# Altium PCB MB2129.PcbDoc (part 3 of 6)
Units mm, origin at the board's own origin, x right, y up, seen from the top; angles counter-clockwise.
Board outline 70 x 133.34 mm, 6 copper layers (Top Layer, Signal Layer 1, Signal Layer 2, Signal Layer 3, Signal Layer 4, Bottom Layer), stack 1.57 mm thick; 377 components, 289 nets, 1482 pads, 1373 vias.
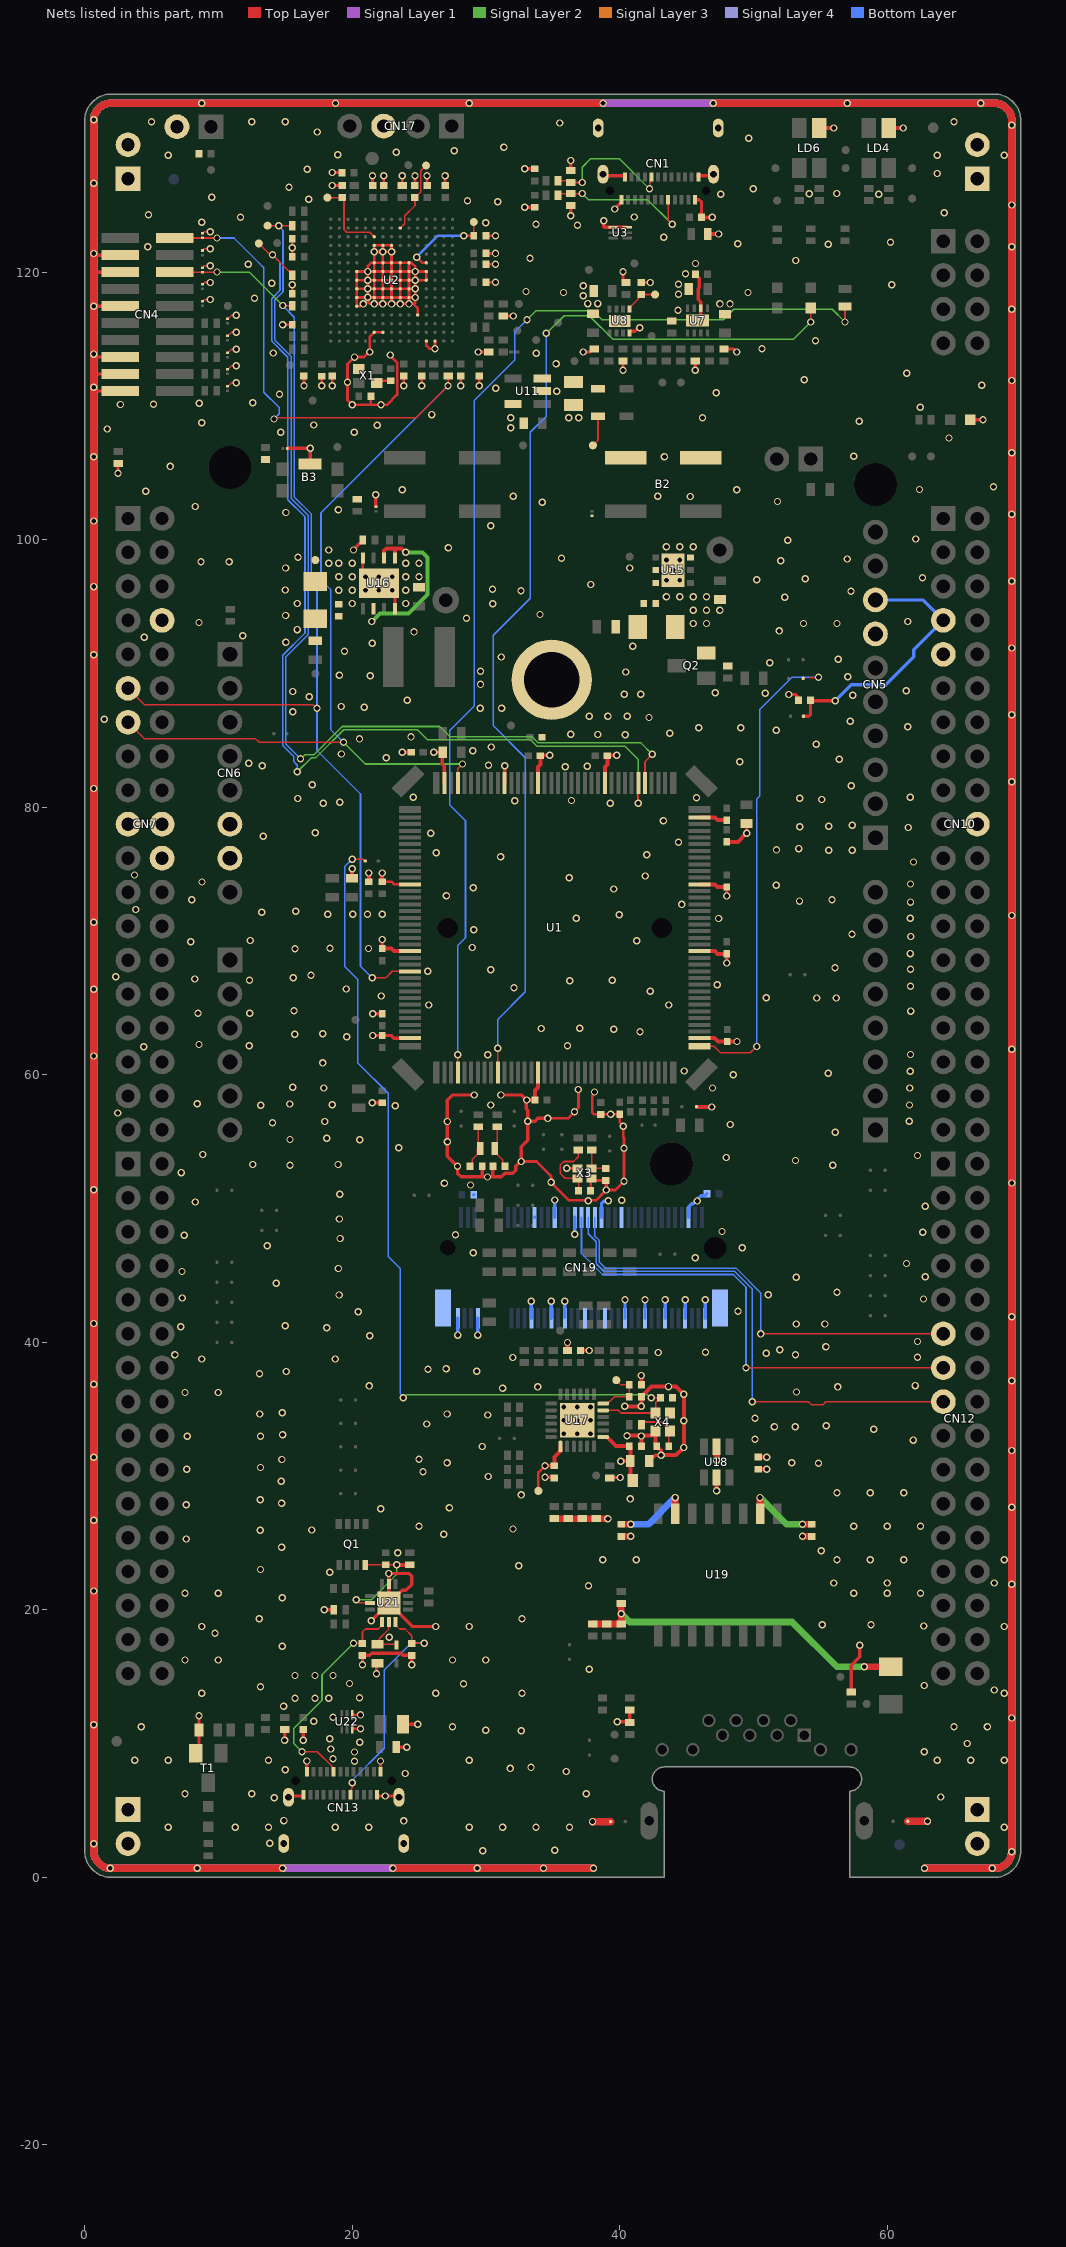
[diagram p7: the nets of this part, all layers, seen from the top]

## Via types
v1: diameter 0.55, hole 0.35, Top Layer to Bottom Layer, tented both sides, 1373 vias

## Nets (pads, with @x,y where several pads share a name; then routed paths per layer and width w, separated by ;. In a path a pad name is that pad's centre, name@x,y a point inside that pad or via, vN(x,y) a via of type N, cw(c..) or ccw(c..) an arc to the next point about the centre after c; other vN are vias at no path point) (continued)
DBGIN.SWDIO: CN4.2 CN7.13 R45.2 U1.105 U24.1 | length 93.5
  Top Layer w0.12: CN7.13@3.246,86.37 4.466,85.15 12.774,85.15 13.049,84.875 17.35,84.875 v1(19.35,84.875) ; CN4.2@6.735,122.565 6.752,122.581 U24.1@8.8,122.581 v1(9.9,122.581) ; v1(14.155,109.046) 14.235,109.127 24.767,109.127 v1(27.17,111.53) ; v1@27.175,111.53 R45.2@27.175,112.25 ; U1.105@27.9,81.825 27.9,82.9 v1(28.25,83.25)
  Signal Layer 2 w0.12: v1(19.35,84.875) 20.975,83.25 v1(28.25,83.25)
  Bottom Layer w0.12: v1(9.9,122.581) 11.168,122.581 13.075,120.675 13.395,120.355 13.395,111.055 14.55,109.9 14.55,109.441 v1(14.155,109.046) ; v1(19.35,84.875) 18.39,85.835 18.39,96.295 17.675,97.01 17.675,102.035 v1(27.17,111.53)
DBGIN.SWO: CN4.6 CN7.11 R22.2 U1.133 U10.1 | length 80.6
  Top Layer w0.12: CN7.11@3.246,88.91 4.489,87.667 17.09,87.667 17.331,87.425 v1(17.375,87.425) ; CN4.6@6.735,120.025 6.742,120.031 U10.1@8.8,120.031 v1(9.9,120.031) ; v1@14.8,117.525 R22.2@15.525,117.525 ; v1(21.5,67.275) 22.526,67.275 23.001,67.75 U1.133@24.325,67.75
  Signal Layer 2 w0.12: v1(9.9,120.031) 12.304,120.031 v1(14.805,117.53)
  Bottom Layer w0.12: v1(14.805,117.53) 15.675,116.66 15.675,103.214 16.955,101.934 16.955,96.712 17.375,96.292 v1(17.375,87.425) 17.375,84.264 20.625,81.014 20.625,68.125 v1@21.45,67.3 ; v1@21.45,67.275 v1(21.5,67.275)
DBGIN.VCP_RX: R20.2 TP17.1 U1.78 | length 77.3
  Top Layer w0.12: TP17.1@13.025,122.175 13.793,121.407 13.968,121.407 15.285,120.09 15.33,120.09 15.525,119.895 R20.2@15.525,119.8 ; v1(41.4,80.325) U1.78@41.4,81.825
  Signal Layer 2 w0.12: v1(15.905,82.671) 16.939,83.705 17.253,83.705 19.363,85.815 24.887,85.815 25.652,85.05 33.35,85.05 33.825,84.575 40.409,84.575 41.4,83.584 v1(41.4,80.325)
  Bottom Layer w0.12: v1(14.05,121.325) 14.61,120.765 14.61,118.674 13.98,118.044 13.98,114.884 15.195,113.669 15.195,103.016 16.475,101.736 16.475,93.039 14.81,91.374 14.81,84.636 15.638,83.808 15.638,83.432 15.905,83.164 v1(15.905,82.671)
DBGIN.VCP_TX: R16.2 TP15.1 U1.77 | length 74.6
  Top Layer w0.12: TP15.1@13.925,123.5 v1(14.525,123.5) R16.2@15.521,123.5 ; U1.77@41.9,81.825 41.9,83.425 v1(42.45,83.975)
  Signal Layer 2 w0.12: v1(16.14,83.645) 16.184,83.645 16.484,83.945 17.154,83.945 19.264,86.055 26.545,86.055 27.31,85.29 33.449,85.29 33.914,84.825 41.6,84.825 v1(42.45,83.975)
  Bottom Layer w0.12: v1(14.525,123.5) 14.525,123.467 14.83,123.162 14.83,118.555 14.2,117.925 14.2,114.975 15.435,113.74 15.435,103.115 16.715,101.835 16.715,92.94 15.05,91.275 15.05,84.735 v1(16.14,83.645)
GND: B2.1 B2.2 B3.5 C1.1 C2.2 C3.1 C4.1 C5.2 C6.2 C7.1 C8.2 C9.2 C10.2 C11.2 C12.1 C13.2 C14.2 C15.2 C16.2 C17.1 C18.2 C19.1 C20.1 C21.1 C22.2 C23.1 C24.1 C25.2 C26.2 C27.2 C28.2 C29.2 C30.2 C31.2 C32.2 C33.2 C34.1 C35.1 C36.1 C37.1 C38.1 C43.1 C44.1 C45.1 C46.1 C47.2 C48.1 C49.1 C50.1 C51.1 C52.1 C53.1 C54.2 C55.1 C57.1 C59.1 C60.1 C61.2 C64.2 C65.1 C66.1 C67.1 C68.1 C71.1 C72.1 C73.1 C74.1 C79.1 C81.1 C82.2 C83.2 C84.1 C85.1 C86.1 C87.1 C88.1 C89.1 C90.1 C91.1 C92.1 C94.1 C95.1 C97.2 C98.2 C99.2 C104.2 C105.1 C106.1 C107.1 CN1.A1 CN1.A12 CN1.B1 CN1.B12 CN1.SH1 CN1.SH2 CN1.SH3 CN1.SH4 CN2.1 CN2.2 CN3.1 CN3.2 CN4.3 CN4.5 CN4.9 CN4.15 CN4.17 CN4.19 CN5.7 CN6.6 CN6.7 CN7.8 CN7.19 CN7.20 CN7.22 CN10.9 CN10.20 CN13.A1 CN13.A12 CN13.B1 CN13.B12 CN13.SH1 CN13.SH2 CN13.SH3 CN13.SH4 CN15.1 CN15.2 CN16.1 CN16.2 CN17.3 CN19.1 CN19.7 CN19.23 CN19.24 CN19.29 CN19.30 CN19.33 CN19.36 CN19.39 CN19.44 CN19.45 CN19.50 CN19.51 CN19.57 CN19.63 CN19.69 CN19.70 CN19.75 CN19.S1 CN19.S2 HW6.1 JP3.2 LD4.3 LD6.3 LD7.2 Q2.2 R5.2 R8.2 R14.2 R21.1 R24.2 R25.1 R30.2 R33.1 R34.2 R39.2 R41.1 R49.1 R50.1 R54.1 R72.2 R81.2 R90.2 R95.1 R96.1 R101.1 R102.1 R103.1 R110.1 R112.2 SB19.1 SB43.2 SB44.2 T1.2 TP46.1 U1.16 U1.38 U1.51 U1.61 U1.71 U1.83 U1.93 U1.98 U1.107 U1.120 U1.130 U1.143 U2.D5 U2.D6 U2.D7 U2.D8 U2.D9 U2.F2 U2.F6 U2.F7 U2.F8 U2.F9 U2.F10 U2.F12 U2.G2 U2.G6 U2.G7 U2.G8 U2.G9 U2.G10 U2.G12 U2.H6 U2.H7 U2.H8 U2.H9 U2.H10 U2.H12 U2.J6 U2.J7 U2.J8 U2.J9 U2.J10 U2.K6 U2.K7 U2.K8 U2.K9 U2.K10 U2.L4 U2.M1 U2.M8 U2.M9 U2.N1 U3.3 U3.4 U4.2 U5.2 U6.2 U7.2 U7.9 U8.8 U8.9 U9.2 U10.2 U11.2 U12.2 U13.2 U14.2 U15.3 U15.EP U16.4 U16.8 U16.9 U17.EP U18.2 U20.2 U21.2 U21.13 U22.3 U22.4 U23.2 U24.2 U25.2 U26.2 U27.2 U28.2 X1.2 X1.4 X3.2 X3.4 X4.2 X4.4 | length 2553.2
  Top Layer w0.12: U6.2@8.8,117.844 8.819,117.844 8.951,117.975 v1(9.4,117.975) ; U5.2@8.8,119.119 8.819,119.119 8.951,119.25 v1(9.4,119.25) ; U10.2@8.8,120.369 8.819,120.369 8.951,120.5 v1(9.4,120.5) ; U20.2@8.8,121.644 8.819,121.644 8.951,121.775 v1(9.4,121.775) ; U24.2@8.8,122.919 8.819,122.919 8.951,123.05 v1(9.4,123.05) ; U28.2@10.7,111.494 10.719,111.494 10.753,111.527 10.986,111.761 ; U27.2@10.7,112.769 10.719,112.769 10.753,112.802 10.986,113.036 ; U26.2@10.7,113.994 10.719,113.994 10.753,114.027 10.986,114.261 ; U25.2@10.7,115.269 10.719,115.269 10.753,115.302 10.986,115.536 ; U9.2@10.7,116.544 10.719,116.544 10.753,116.577 10.986,116.811 ; 11.012,111.761 10.986,111.761 ; 11.012,113.036 10.986,113.036 ; 11.012,114.261 10.986,114.261 ; 11.012,115.536 10.986,115.536 ; 11.012,116.811 10.986,116.811 ; v1(11.325,111.75) 11.314,111.761 10.986,111.761 ; v1(11.325,113.025) 11.314,113.036 10.986,113.036 ; v1(11.325,114.25) 11.314,114.261 10.986,114.261 ; v1(11.325,115.525) 11.314,115.536 10.986,115.536 ; v1(11.325,116.8) 11.314,116.811 10.986,116.811
  Top Layer w0.2: v1(2.5,105) R50.1@2.5,105.725 ; v1(14.8,116.1) C25.2@15.525,116.1 ; C13.2@15.521,122.525 15.524,122.522 15.524,121.851 v1(15.528,121.847) v1(15.528,121.847) 15.526,121.176 C15.2@15.525,121.175 v1@15.525,121.845 ; C22.2@15.525,118.4 v1@15.525,119.07 ; v1(16.4,111.525) C26.2@16.4,112.25 ; v1(17.725,111.52) C32.2@17.725,112.245 ; v1(18.525,111.525) C27.2@18.525,112.25 ; v1(18.525,126.5) C4.1@19.25,126.5 ; v1(18.525,127.475) C3.1@19.25,127.475 ; U22.3@20.02,11.11 20.625,11.11 v1(20.625,11.125) ; U22.4@20.02,12.16 20.625,12.16 v1(20.625,12.15) ; U16.4@20.8,98.65 20.8,97.45 v1(21,97.25) ; C35.1@21.4,110.75 21.4,110.1 ; C5.2@21.525,126.5 v1(21.525,127.225) ; X1.2@21.85,111.75 22,111.9 C33.2@22.875,111.9 ; C50.1@22.275,74.45 22.95,74.45 23.15,74.25 U1.120@24.325,74.25 ; U2.G2@22.3,115.525 U2.F2@21.65,115.525 21.325,115.2 v1(21.325,114.05) 21.262,114.05 20.887,113.675 v1(20.175,113.675) 19.65,113.15 19.65,110.45 v1(20,110.1) 21.4,110.1 ; C6.2@22.375,126.5 v1(22.375,127.225) ; v1(22.85,113.825) 22.85,113.782 23.37,113.262 23.37,110.87 22.6,110.1 21.4,110.1 ; v1(23,96.25) 23.2,96.05 23.2,95.775 U16.8@23.2,94.85 ; R8.2@23.75,126.5 v1(23.75,127.225) ; v1(23.85,111.525) C28.2@23.85,112.25 ; C7.1@24.7,126.5 v1(24.7,127.225) ; U2.L4@24.9,116.825 24.9,117.35 24.6,117.65 ; v1(25.2,111.525) C29.2@25.2,112.25 ; U2.M1@25.55,114.875 25.55,114.525 25.775,114.3 v1(26.2,114.3) U2.N1@26.2,114.875 ; C8.2@25.6,126.5 v1(25.6,127.225) ; C9.2@26.95,126.5 v1(26.95,127.225) ; v1(28.125,111.525) C31.2@28.125,112.25 ; v1(29.425,114.05) R30.2@30.225,114.05 ; v1(29.5,111.525) C30.2@29.5,112.25 ; C18.2@30,119.275 v1(30.725,119.275) ; C16.2@30,120.625 v1(30.725,120.625) ; C14.2@30,121.425 v1(30.725,121.425) ; C12.1@30,122.75 v1(30.725,122.75) ; R24.2@31.3,116.75 v1(32.05,116.75) ; v1@32.65,53.625 32.65,53.6 v1(32.65,53.525) 33.8,53.525 34.875,52.45 v1(34.875,51.975) 36.228,50.622 38.222,50.622 v1(39,51.4) 39.68,51.4 40.325,52.045 v1(40.325,52.05) v1(40.325,54.525) 40.325,55.3 40.275,55.35 v1(40.275,56.175) ; v1(34.625,56.75) 34.633,56.758 36.133,56.758 v1(36.625,57.25) 36.925,57.55 v1@36.925,58.89 ; v1(36.05,53.025) 36.845,53.025 X3.4@36.856,53.014 ; C83.2@37.831,51.339 37.831,52.189 X3.2@37.906,52.264 38.056,52.114 C82.2@38.956,52.114 ; v1(38.125,58.725) 38.125,58.63 37.989,58.495 37.989,58.447 37.95,58.408 37.95,57.2 38.1,57.05 C73.1@38.6,57.05 v1(39.325,57.05) C74.1@39.95,57.05 ; C74.1@40,57.05 40,56.467 40.275,56.192 v1(40.275,56.175) ; v1@40.325,56.125 v1(40.275,56.175) ; U2.D6@20.35,118.125 21.15,118.125 v1(21.175,118.15) ; U2.D6@20.35,118.125 U2.D7@20.35,118.775 ; U2.D6@20.35,118.125 U2.D5@20.35,117.475 20.356,117.481 20.616,117.481 20.785,117.65 v1(20.825,117.65) 20.825,117.675 20.857,117.707 21.057,117.707 21.175,117.825 ; U2.D7@20.35,118.775 v1(21.175,118.775) ; U2.D7@20.35,118.775 U2.D8@20.35,119.425 ; U2.D8@20.35,119.425 v1(21.175,119.425) ; U2.D8@20.35,119.425 U2.D9@20.35,120.075 v1(21.175,120.075) ; 21.175,117.825 v1(21.175,118.15) ; 21.175,117.825 21.35,117.65 v1(21.65,117.65) ; v1(21.175,118.15) v1(21.175,118.775) ; v1(21.175,118.15) 21.2,118.125 U2.F6@21.65,118.125 ; v1(21.175,118.775) U2.F7@21.65,118.775 ; v1(21.175,118.775) v1(21.175,119.425) ; v1(21.175,119.425) U2.F8@21.65,119.425 ; v1(21.175,119.425) v1(21.175,120.075) ; v1(21.175,120.075) U2.F9@21.65,120.075 ; v1(21.175,120.075) 21.175,120.496 21.404,120.725 U2.F10@21.65,120.725 ; v1(21.65,117.65) U2.F6@21.65,118.125 ; v1(21.65,117.65) v1(22.3,117.65) ; U2.F6@21.65,118.125 U2.G6@22.3,118.125 ; U2.F6@21.65,118.125 U2.F7@21.65,118.775 ; U2.F7@21.65,118.775 U2.F8@21.65,119.425 ; U2.F7@21.65,118.775 U2.G7@22.3,118.775 ; U2.F8@21.65,119.425 U2.F9@21.65,120.075 ; U2.F8@21.65,119.425 U2.G8@22.3,119.425 ; U2.F9@21.65,120.075 U2.F10@21.65,120.725 ; U2.F9@21.65,120.075 U2.G9@22.3,120.075 ; U2.F10@21.65,120.725 v1(21.65,121.55) ; U2.F10@21.65,120.725 U2.G10@22.3,120.725 ; v1(21.65,121.55) U2.F12@21.65,122.025 U2.G12@22.3,122.025 ; v1(21.65,121.55) v1(22.3,121.55) ; v1(22.3,117.65) U2.G6@22.3,118.125 ; v1(22.3,117.65) v1(22.95,117.65) ; U2.G6@22.3,118.125 U2.H6@22.95,118.125 ; U2.G6@22.3,118.125 U2.G7@22.3,118.775 ; U2.G7@22.3,118.775 U2.G8@22.3,119.425 ; U2.G7@22.3,118.775 U2.H7@22.95,118.775 ; U2.G8@22.3,119.425 U2.G9@22.3,120.075 ; U2.G8@22.3,119.425 U2.H8@22.95,119.425 ; U2.G9@22.3,120.075 U2.G10@22.3,120.725 ; U2.G9@22.3,120.075 U2.H9@22.95,120.075 ; U2.G10@22.3,120.725 v1(22.3,121.55) ; U2.G10@22.3,120.725 U2.H10@22.95,120.725 ; v1(22.3,121.55) U2.G12@22.3,122.025 ; v1(22.3,121.55) v1(22.95,121.55) ; U2.G12@22.3,122.025 U2.H12@22.95,122.025 v1(22.95,121.55) ; v1(22.95,117.65) U2.H6@22.95,118.125 ; v1(22.95,117.65) v1(23.6,117.65) ; U2.H6@22.95,118.125 U2.J6@23.6,118.125 ; U2.H6@22.95,118.125 U2.H7@22.95,118.775 ; U2.H7@22.95,118.775 U2.H8@22.95,119.425 ; U2.H7@22.95,118.775 U2.J7@23.6,118.775 ; U2.H8@22.95,119.425 U2.H9@22.95,120.075 ; U2.H8@22.95,119.425 U2.J8@23.6,119.425 ; U2.H9@22.95,120.075 U2.H10@22.95,120.725 ; U2.H9@22.95,120.075 U2.J9@23.6,120.075 ; U2.H10@22.95,120.725 v1(22.95,121.55) ; U2.H10@22.95,120.725 U2.J10@23.6,120.725 ; v1(23.6,117.65) U2.J6@23.6,118.125 ; v1(23.6,117.65) v1(24.25,117.65) ; U2.J6@23.6,118.125 U2.J7@23.6,118.775 ; U2.J6@23.6,118.125 U2.K6@24.25,118.125 ; U2.J7@23.6,118.775 U2.J8@23.6,119.425 ; U2.J7@23.6,118.775 U2.K7@24.25,118.775 ; U2.J8@23.6,119.425 U2.J9@23.6,120.075 ; U2.J8@23.6,119.425 U2.K8@24.25,119.425 ; U2.J9@23.6,120.075 U2.J10@23.6,120.725 ; U2.J9@23.6,120.075 U2.K9@24.25,120.075 ; U2.J10@23.6,120.725 U2.K10@24.25,120.725 ; v1(24.25,117.65) U2.K6@24.25,118.125 ; v1(24.25,117.65) 24.6,117.65 ; U2.K6@24.25,118.125 v1(24.725,118.125) ; U2.K6@24.25,118.125 U2.K7@24.25,118.775 ; U2.K7@24.25,118.775 v1(24.725,118.775) ; U2.K7@24.25,118.775 U2.K8@24.25,119.425 ; U2.K8@24.25,119.425 U2.K9@24.25,120.075 ; U2.K8@24.25,119.425 v1(24.725,119.425) ; U2.K9@24.25,120.075 U2.K10@24.25,120.725 ; U2.K9@24.25,120.075 v1(24.725,120.075) ; U2.K10@24.25,120.725 24.45,120.725 24.725,120.45 v1(24.725,120.075) ; 24.6,117.65 24.725,117.775 v1(24.725,118.125) ; v1(24.725,118.125) v1(24.725,118.775) ; v1(24.725,118.775) v1(24.725,119.425) ; v1(24.725,119.425) U2.M8@25.55,119.425 U2.M9@25.55,120.075 v1(24.725,120.075) ; v1(24.725,119.425) v1(24.725,120.075)
  Top Layer w0.25: 0.675,111.046 0.764,111.135 CN4.19@2.665,111.135 ; 0.675,112.377 0.703,112.405 CN4.17@2.665,112.405 ; 0.675,113.55 0.8,113.675 CN4.15@2.665,113.675 ; v1@0.675,117.483 v1(0.677,117.485) CN4.9@2.665,117.485 ; 0.675,120.034 0.684,120.025 CN4.5@2.665,120.025 ; v1(0.675,121.416) 0.756,121.416 0.877,121.295 CN4.3@2.665,121.295 ; T1.2@8.3,9.275 8.55,9.525 R103.1@8.55,11.025 v1(8.55,12.1) ; v1(14.95,10.25) R101.1@14.95,11.05 ; U12.2@15.15,106.85 v1(16.875,106.85) 16.875,105.7 B3.5@16.85,105.675 ; CN13.SH1@15.24,5.985 15.345,6.09 16.345,6.09 16.37,6.115 CN13.B12@16.37,6.195 ; v1(16.35,10.25) C105.1@16.35,11.05 ; CN13.A1@16.62,7.895 v1(16.62,8.71) ; v1(17.925,20.025) R90.2@18.625,20.025 ; v1(20.1,99.25) 20.625,99.775 20.67,99.775 20.8,99.905 R54.1@20.8,99.95 ; v1(20.775,15.9) C97.2@20.775,16.6 21.3,16.6 21.45,16.75 23.65,16.75 23.8,16.6 C98.2@24.45,16.6 v1(24.45,15.9) ; v1(21.425,19.2) U21.13@22.75,20.525 ; v1(21.5,57.925) 22.15,57.925 C68.1@22.175,57.95 ; v1(21.55,62.95) 22.925,62.95 23.125,62.75 U1.143@24.325,62.75 ; v1(21.55,64.575) C64.2@22.25,64.575 ; U13.2@21.775,102.509 v1(21.775,103.387) ; v1(21.825,15.225) 21.825,15.95 C99.2@21.9,16.025 ; CN13.B1@21.87,6.195 21.87,6.115 21.895,6.09 v1(22.468,6.09) 23.395,6.09 CN13.SH2@23.5,5.985 ; v1(22,96.25) 22.15,96.1 22.875,96.1 U16.9@23.2,95.775 ; CN13.A12@22.12,7.895 v1(22.12,8.71) ; C53.1@22.25,69.425 C53.1@22.25,69.45 v1(22.25,70.125) ; U23.2@23.295,9.735 v1(24.095,9.735) ; v1(23.75,84.125) C65.1@24.425,84.125 ; C104.2@23.82,11.46 v1(24.895,11.46) ; v1(26.1,84.125) C59.1@26.775,84.125 ; v1(26.25,18.759) 24.516,18.759 U21.13@22.75,20.525 ; C59.1@26.775,84 C59.1@26.775,84.125 ; U1.107@26.9,81.85 26.9,83.075 26.75,83.225 26.75,84.1 C59.1@26.775,84.125 ; v1(27.125,56.525) 27.125,54.975 27.125,53.925 v1(27.875,53.175) 27.875,52.65 28.145,52.38 29.725,52.38 ; v1@27.125,56.55 27.125,58.125 27.5,58.5 v1(29.125,58.5) ; C79.1@29.725,53.18 29.725,52.38 ; C81.1@30.525,53.18 30.525,52.38 ; v1(31.125,58.5) 31.13,58.505 32.645,58.505 33.025,58.125 33.025,57.45 33.125,57.35 v1(33.125,56.55) ; U1.98@31.4,81.825 v1(31.4,83.125) ; v1@32.65,53.6 32.225,53.175 32.225,52.871 32.009,52.655 31.43,52.655 31.155,52.38 30.525,52.38 ; v1@32.65,53.625 32.65,54.63 33.125,55.105 v1(33.125,56.55) ; v1(32.9,124.875) C10.2@33.65,124.875 ; v1(32.9,127.75) C2.2@33.65,127.75 ; C51.1@34.075,83.9 34.1,83.9 v1(34.775,83.9) ; v1(34.425,29.925) 35.075,29.925 C92.1@35.125,29.875 ; v1(34.625,56.75) 33.875,56.75 33.675,56.55 v1(33.125,56.55) ; v1(36.35,124.25) R14.2@36.35,125 ; R5.2@36.35,127.625 v1(36.35,128.375) ; v1(36.9,58.915) v1@36.925,58.89 ; v1(37.275,114.05) 37.78,114.05 38.005,114.275 R33.1@38.1,114.275 ; CN1.SH2@38.755,127.35 38.86,127.245 40.36,127.245 40.385,127.22 CN1.B1@40.385,127.14 ; v1(38.825,123.875) 38.825,123.426 38.876,123.375 U3.4@39.525,123.375 U3.3@40.575,123.375 ; C82.2@38.956,52.114 39,52.07 v1(39,51.4) ; C52.1@39.075,83.9 39.1,83.9 v1(39.775,83.9) ; R81.2@39.211,29.875 R81.2@39.275,29.875 ; R81.2@39.5,29.9 v1(40.05,29.9) ; v1(39.625,124.75) 39.645,124.75 40.135,125.24 CN1.A12@40.135,125.44 ; v1(39.825,11.65) 40.675,11.65 R102.1@40.745,11.58 ; v1(40.25,112.7) R34.2@40.25,113.375 ; v1(40.25,120.05) 40.25,119.38 40.38,119.25 R21.1@40.475,119.25 ; R102.1@40.745,11.562 R102.1@40.745,11.58 ; R96.1@40.748,12.523 40.745,12.52 R102.1@40.745,11.58 ; R102.1@40.75,11.575 R102.1@40.745,11.58 ; U8.8@40.75,115.475 40.75,115.575 40.775,115.6 41.144,115.6 41.419,115.875 v1(41.5,115.875) ; C19.1@41.625,119.25 v1(42.3,119.25) ; C91.1@42.2,31.125 42.65,31.575 v1(43.1,31.575) ; CN1.A1@45.635,125.44 45.927,125.44 46.125,125.242 C11.2@46.125,124.125 ; v1(45.65,112.7) R39.2@45.65,113.375 ; C17.1@45.675,119.875 45.675,119.85 45.95,119.575 45.95,118.85 45.875,118.775 45.875,117.992 46.075,117.792 U7.2@46.075,117.325 46.075,116.65 U7.9@45.825,116.4 ; CN1.B12@45.885,127.14 45.885,127.22 45.91,127.245 46.91,127.245 CN1.SH1@47.015,127.35 ; R41.1@47.8,114.275 48.525,114.275 v1(48.75,114.05) ; v1(48,68.375) C60.1@48,69.05 C60.1@48,69.075 ; v1(48,73.375) C71.1@48,74.05 C71.1@48,74.075 ; C57.1@48,79.05 C57.1@48,79.075 ; v1(49.5,78.075) C48.1@49.5,78.8 ; v1(52.65,88.45) 53.125,88.45 53.375,88.2 C47.2@53.375,88 ; R95.1@57.325,13.875 57.325,15.85 57.96,16.485 v1(57.96,17.36) ; LD7.2@66.225,109 v1(67.175,109) ; U21.13@22.75,20.525 23.475,21.25 23.529,21.25 23.743,21.464 24.014,21.464 24.45,21.9 24.45,22.525 24.25,22.725 v1(22.75,22.725) U21.2@22.75,21.95 U21.13@22.75,20.525 ; 29.725,52.38 30.525,52.38
  Top Layer w0.3: C49.1@20,74.7 v1(20,75.425) ; C55.1@21.25,74.45 v1(21.25,75.1) ; C53.1@22.25,69.45 22.925,69.45 23.125,69.25 U1.130@24.275,69.25 ; C50.1@22.25,74.45 v1(22.25,75.1) ; v1(33.05,58.125) C72.1@33.675,58.125 33.675,58.85 33.9,59.075 U1.16@33.9,60.175 ; U1.93@33.9,81.875 33.9,83.025 34.1,83.225 C51.1@34.1,83.9 ; R72.2@36.1,39.4 v1(36.1,40.001) ; C84.1@37.075,39.4 v1(37.725,39.4) ; U1.83@38.9,81.875 38.9,83.025 39.1,83.225 C52.1@39.1,83.9 ; v1(40.375,35.225) v1(41.625,35.225) C86.1@41.625,35.95 42.375,36.7 v1(43.65,36.7) 44.225,36.7 v1(44.8,36.125) v1(44.8,34.138) v1(44.8,32.15) 44.225,31.575 v1(43.1,31.575) 43.1,31.925 C89.1@42.775,32.25 42.7,32.325 X4.4@42.7,33.375 42.35,33.025 41.65,33.025 v1(41.625,33) ; v1(40.55,33.025) 41.6,33.025 v1(41.625,33) ; C88.1@41.625,32.25 v1(41.625,33) ; C85.1@41.625,36.825 v1(41.625,37.525) ; 45.95,57.6 v1(46.9,57.6) ; U1.38@45.975,62.75 47.1,62.75 47.35,62.5 C66.1@48,62.5 ; U1.51@45.975,69.25 47.125,69.25 47.325,69.05 C60.1@48,69.05 ; U1.61@45.975,74.25 47.125,74.25 47.325,74.05 C71.1@48,74.05 ; U1.71@45.975,79.25 47.125,79.25 47.325,79.05 C57.1@48,79.05 ; C11.2@46.125,124.125 v1(46.925,124.125) ; U4.2@46.6,122.875 v1(47.4,122.875) ; v1(47.25,28.9) U18.2@47.25,29.9 ; C61.2@48,77.425 48.85,77.425 v1(49.5,78.075) ; C66.1@48.05,62.5 v1(48.775,62.5) ; C90.1@50.35,30.525 v1(51,30.525) ; LD6.3@54.925,130.8 v1(56,130.8) ; LD4.3@60.125,130.8 v1(61.2,130.8)
  Top Layer w0.5: C94.1@40.125,25.5 v1(40.825,25.5) ; v1(53.675,25.5) C95.1@54.375,25.5
  Top Layer w0.55: v1(14.8,0.675) v1(8.424,0.675) v1(1.924,0.675) cw(c1.924,1.225) 1.817,0.685 1.666,0.715 cw(c1.774,1.255) 1.564,0.746 1.421,0.806 cw(c1.633,1.313) 1.329,0.855 1.199,0.941 cw(c1.506,1.398) 1.118,1.008 1.008,1.118 cw(c1.398,1.506) 0.941,1.199 0.855,1.329 cw(c1.313,1.633) 0.806,1.421 0.746,1.564 cw(c1.255,1.774) 0.715,1.666 0.685,1.817 cw(c1.225,1.924) 0.675,1.924 v1(0.675,2.524) v1(0.675,11.416) v1(0.675,26.707) v1(0.675,36.868) 0.675,41.427 v1(0.675,51.416) v1(0.675,61.416) v1(0.675,66.416) v1(0.675,71.416) v1(0.675,81.416) v1(0.675,91.416) v1(0.675,96.515) v1(0.675,101.416) v1(0.675,106.231) 0.675,111.046 v1(0.675,111.416) 0.675,112.377 0.675,113.55 v1(0.675,113.899) 0.675,117.483 0.675,120.034 v1(0.675,121.416) v1(0.675,126.671) v1(0.675,131.416) cw(c1.225,131.416) 0.686,131.524 0.715,131.673 cw(c1.255,131.566) 0.747,131.777 0.806,131.919 cw(c1.313,131.707) 0.855,132.012 0.941,132.14 cw(c1.398,131.834) 1.008,132.222 1.118,132.332 cw(c1.506,131.942) 1.2,132.399 1.327,132.484 cw(c1.633,132.027) 1.422,132.535 1.563,132.593 cw(c1.774,132.085) 1.667,132.625 1.817,132.655 cw(c1.924,132.115) 1.924,132.665 v1(8.76,132.665) v1(18.76,132.665) v1(28.76,132.665) v1(38.76,132.665) ; v1(23.05,0.675) v1(29.358,0.675) v1(34.313,0.675) v1(38.05,0.675) ; v1(37.975,4.175) SB44.2@39.325,4.175 ; v1(47.01,132.665) v1(57.01,132.665) v1(67.01,132.665) 68.076,132.665 cw(c68.076,132.115) 68.184,132.654 68.333,132.625 cw(c68.226,132.085) 68.437,132.593 68.578,132.535 cw(c68.367,132.027) 68.673,132.484 68.8,132.399 cw(c68.494,131.942) 68.883,132.331 68.991,132.223 cw(c68.602,131.834) 69.059,132.14 69.144,132.013 cw(c68.687,131.707) 69.195,131.918 69.253,131.777 cw(c68.745,131.566) 69.285,131.673 69.314,131.524 cw(c68.775,131.416) 69.325,131.416 v1(69.325,131.002) v1(69.325,125.045) v1(69.325,121.924) v1(69.325,117.239) v1(69.325,111.924) v1(69.325,106.52) v1(69.325,101.924) v1(69.325,96.924) v1(69.325,91.924) v1(69.325,86.924) v1(69.325,81.924) v1(69.325,71.924) v1(69.325,61.924) v1(69.325,51.924) v1(69.325,41.924) v1(69.325,37.141) v1(69.325,31.924) v1(69.325,27.682) v1(69.325,21.924) v1(69.325,11.924) v1(69.325,1.924) ; SB43.2@61.55,4.2 v1(63.025,4.2) ; v1(62.8,0.675) v1(67.867,0.675) 68,0.675 68.13,0.675 68.386,0.726 68.628,0.826 68.723,0.89 68.845,0.971 69.029,1.155 69.174,1.372 69.274,1.613 69.325,1.869 v1@69.325,1.901
  Signal Layer 1 w0.55: v1(38.05,0.675) v1(34.313,0.675) v1(29.358,0.675) 26.55,0.675 v1(23.05,0.675) v1(14.8,0.675) v1(8.424,0.675) v1(1.924,0.675) cw(c1.924,1.225) 1.817,0.685 1.666,0.715 cw(c1.774,1.255) 1.564,0.746 1.421,0.806 cw(c1.633,1.313) 1.329,0.855 1.199,0.941 cw(c1.506,1.398) 1.118,1.008 1.008,1.118 cw(c1.398,1.506) 0.941,1.199 0.855,1.329 cw(c1.313,1.633) 0.806,1.421 0.746,1.564 cw(c1.255,1.774) 0.715,1.666 0.685,1.817 cw(c1.225,1.924) 0.675,1.924 v1(0.675,2.524) v1(0.675,11.416) v1(0.675,26.707) v1(0.675,36.868) 0.675,41.427 v1(0.675,51.416) v1(0.675,61.416) v1(0.675,66.416) v1(0.675,71.416) v1(0.675,81.416) v1(0.675,91.416) v1(0.675,96.515) v1(0.675,101.416) v1(0.675,106.231) v1(0.675,111.416) v1(0.675,113.899) v1(0.675,121.416) v1(0.675,126.671) v1(0.675,131.416) cw(c1.225,131.416) 0.686,131.524 0.715,131.673 cw(c1.255,131.566) 0.747,131.777 0.806,131.919 cw(c1.313,131.707) 0.855,132.012 0.941,132.14 cw(c1.398,131.834) 1.008,132.222 1.118,132.332 cw(c1.506,131.942) 1.2,132.399 1.327,132.484 cw(c1.633,132.027) 1.422,132.535 1.563,132.593 cw(c1.774,132.085) 1.667,132.625 1.817,132.655 cw(c1.924,132.115) 1.924,132.665 v1(8.76,132.665) v1(18.76,132.665) v1(28.76,132.665) v1(38.76,132.665) v1(47.01,132.665) v1(57.01,132.665) v1(67.01,132.665) 68.076,132.665 cw(c68.076,132.115) 68.184,132.654 68.333,132.625 cw(c68.226,132.085) 68.437,132.593 68.578,132.535 cw(c68.367,132.027) 68.673,132.484 68.8,132.399 cw(c68.494,131.942) 68.883,132.331 68.991,132.223 cw(c68.602,131.834) 69.059,132.14 69.144,132.013 cw(c68.687,131.707) 69.195,131.918 69.253,131.777 cw(c68.745,131.566) 69.285,131.673 69.314,131.524 cw(c68.775,131.416) 69.325,131.416 v1(69.325,131.002) v1(69.325,125.045) v1(69.325,121.924) v1(69.325,117.239) v1(69.325,111.924) v1(69.325,106.52) v1(69.325,101.924) v1(69.325,96.924) v1(69.325,91.924) v1(69.325,86.924) v1(69.325,81.924) v1(69.325,71.924) v1(69.325,61.924) v1(69.325,51.924) v1(69.325,41.924) v1(69.325,37.141) v1(69.325,31.924) v1(69.325,27.682) v1(69.325,21.924) v1(69.325,11.924) v1(69.325,1.924) ; v1(62.8,0.675) v1(67.867,0.675) 68,0.675 68.13,0.675 68.386,0.726 68.518,0.78 68.551,0.794 68.628,0.826 68.845,0.971 69.029,1.155 69.174,1.372 69.274,1.613 v1@69.325,1.869
  Signal Layer 2 w0.55: v1(38.05,0.675) v1(34.313,0.675) v1(29.358,0.675) 26.55,0.675 v1(23.05,0.675) v1(14.8,0.675) v1(8.424,0.675) v1(1.924,0.675) cw(c1.924,1.225) 1.817,0.685 1.666,0.715 cw(c1.774,1.255) 1.564,0.746 1.421,0.806 cw(c1.633,1.313) 1.329,0.855 1.199,0.941 cw(c1.506,1.398) 1.118,1.008 1.008,1.118 cw(c1.398,1.506) 0.941,1.199 0.855,1.329 cw(c1.313,1.633) 0.806,1.421 0.746,1.564 cw(c1.255,1.774) 0.715,1.666 0.685,1.817 cw(c1.225,1.924) 0.675,1.924 v1(0.675,2.524) v1(0.675,11.416) v1(0.675,26.707) v1(0.675,36.868) 0.675,41.427 v1(0.675,51.416) v1(0.675,61.416) v1(0.675,66.416) v1(0.675,71.416) v1(0.675,81.416) v1(0.675,91.416) v1(0.675,96.515) v1(0.675,101.416) v1(0.675,106.231) v1(0.675,111.416) v1(0.675,113.899) v1(0.675,121.416) v1(0.675,126.671) v1(0.675,131.416) cw(c1.225,131.416) 0.686,131.524 0.715,131.673 cw(c1.255,131.566) 0.747,131.777 0.806,131.919 cw(c1.313,131.707) 0.855,132.012 0.941,132.14 cw(c1.398,131.834) 1.008,132.222 1.118,132.332 cw(c1.506,131.942) 1.2,132.399 1.327,132.484 cw(c1.633,132.027) 1.422,132.535 1.563,132.593 cw(c1.774,132.085) 1.667,132.625 1.817,132.655 cw(c1.924,132.115) 1.924,132.665 v1(8.76,132.665) v1(18.76,132.665) v1(28.76,132.665) v1(38.76,132.665) v1(47.01,132.665) v1(57.01,132.665) v1(67.01,132.665) 68.076,132.665 cw(c68.076,132.115) 68.184,132.654 68.333,132.625 cw(c68.226,132.085) 68.437,132.593 68.578,132.535 cw(c68.367,132.027) 68.673,132.484 68.8,132.399 cw(c68.494,131.942) 68.883,132.331 68.991,132.223 cw(c68.602,131.834) 69.059,132.14 69.144,132.013 cw(c68.687,131.707) 69.195,131.918 69.253,131.777 cw(c68.745,131.566) 69.285,131.673 69.314,131.524 cw(c68.775,131.416) 69.325,131.416 v1(69.325,131.002) v1(69.325,125.045) v1(69.325,121.924) v1(69.325,117.239) v1(69.325,111.924) v1(69.325,106.52) v1(69.325,101.924) v1(69.325,96.924) v1(69.325,91.924) v1(69.325,86.924) v1(69.325,81.924) v1(69.325,71.924) v1(69.325,61.924) v1(69.325,51.924) v1(69.325,41.924) v1(69.325,37.141) v1(69.325,31.924) v1(69.325,27.682) v1(69.325,21.924) v1(69.325,11.924) v1(69.325,1.924) ; v1(62.8,0.675) v1(67.867,0.675) 68,0.675 68.13,0.675 68.386,0.726 68.615,0.821 68.628,0.826 68.845,0.971 69.029,1.155 69.174,1.372 69.274,1.613 69.325,1.869 v1@69.325,1.901
  Signal Layer 3 w0.55: v1(38.05,0.675) v1(34.313,0.675) v1(29.358,0.675) 26.55,0.675 v1(23.05,0.675) v1(14.8,0.675) v1(8.424,0.675) v1(1.924,0.675) cw(c1.924,1.225) 1.817,0.685 1.666,0.715 cw(c1.774,1.255) 1.564,0.746 1.421,0.806 cw(c1.633,1.313) 1.329,0.855 1.199,0.941 cw(c1.506,1.398) 1.118,1.008 1.008,1.118 cw(c1.398,1.506) 0.941,1.199 0.855,1.329 cw(c1.313,1.633) 0.806,1.421 0.746,1.564 cw(c1.255,1.774) 0.715,1.666 0.685,1.817 cw(c1.225,1.924) 0.675,1.924 v1(0.675,2.524) v1(0.675,11.416) v1(0.675,26.707) v1(0.675,36.868) 0.675,41.427 v1(0.675,51.416) v1(0.675,61.416) v1(0.675,66.416) v1(0.675,71.416) v1(0.675,81.416) v1(0.675,91.416) v1(0.675,96.515) v1(0.675,101.416) v1(0.675,106.231) v1(0.675,111.416) v1(0.675,113.899) v1(0.675,121.416) v1(0.675,126.671) v1(0.675,131.416) cw(c1.225,131.416) 0.686,131.524 0.715,131.673 cw(c1.255,131.566) 0.747,131.777 0.806,131.919 cw(c1.313,131.707) 0.855,132.012 0.941,132.14 cw(c1.398,131.834) 1.008,132.222 1.118,132.332 cw(c1.506,131.942) 1.2,132.399 1.327,132.484 cw(c1.633,132.027) 1.422,132.535 1.563,132.593 cw(c1.774,132.085) 1.667,132.625 1.817,132.655 cw(c1.924,132.115) 1.924,132.665 v1(8.76,132.665) v1(18.76,132.665) v1(28.76,132.665) v1(38.76,132.665) v1(47.01,132.665) v1(57.01,132.665) v1(67.01,132.665) 68.076,132.665 cw(c68.076,132.115) 68.184,132.654 68.333,132.625 cw(c68.226,132.085) 68.437,132.593 68.578,132.535 cw(c68.367,132.027) 68.673,132.484 68.8,132.399 cw(c68.494,131.942) 68.883,132.331 68.991,132.223 cw(c68.602,131.834) 69.059,132.14 69.144,132.013 cw(c68.687,131.707) 69.195,131.918 69.253,131.777 cw(c68.745,131.566) 69.285,131.673 69.314,131.524 cw(c68.775,131.416) 69.325,131.416 v1(69.325,131.002) v1(69.325,125.045) v1(69.325,121.924) v1(69.325,117.239) v1(69.325,111.924) v1(69.325,106.52) v1(69.325,101.924) v1(69.325,96.924) v1(69.325,91.924) v1(69.325,86.924) v1(69.325,81.924) v1(69.325,71.924) v1(69.325,61.924) v1(69.325,51.924) v1(69.325,41.924) v1(69.325,37.141) v1(69.325,31.924) v1(69.325,27.682) v1(69.325,21.924) v1(69.325,11.924) v1(69.325,1.924) ; v1(62.8,0.675) v1(67.867,0.675) 68,0.675 68.13,0.675 68.386,0.726 68.628,0.826 68.736,0.898 68.845,0.971 69.029,1.155 69.174,1.372 69.274,1.613 v1@69.325,1.869
  Signal Layer 4 w0.55: v1(38.05,0.675) v1(34.313,0.675) v1(29.358,0.675) 26.55,0.675 v1(23.05,0.675) v1(14.8,0.675) v1(8.424,0.675) v1(1.924,0.675) cw(c1.924,1.225) 1.817,0.685 1.666,0.715 cw(c1.774,1.255) 1.564,0.746 1.421,0.806 cw(c1.633,1.313) 1.329,0.855 1.199,0.941 cw(c1.506,1.398) 1.118,1.008 1.008,1.118 cw(c1.398,1.506) 0.941,1.199 0.855,1.329 cw(c1.313,1.633) 0.806,1.421 0.746,1.564 cw(c1.255,1.774) 0.715,1.666 0.685,1.817 cw(c1.225,1.924) 0.675,1.924 v1(0.675,2.524) v1(0.675,11.416) v1(0.675,26.707) v1(0.675,36.868) 0.675,41.427 v1(0.675,51.416) v1(0.675,61.416) v1(0.675,66.416) v1(0.675,71.416) v1(0.675,81.416) v1(0.675,91.416) v1(0.675,96.515) v1(0.675,101.416) v1(0.675,106.231) v1(0.675,111.416) v1(0.675,113.899) v1(0.675,121.416) v1(0.675,126.671) v1(0.675,131.416) cw(c1.225,131.416) 0.686,131.524 0.715,131.673 cw(c1.255,131.566) 0.747,131.777 0.806,131.919 cw(c1.313,131.707) 0.855,132.012 0.941,132.14 cw(c1.398,131.834) 1.008,132.222 1.118,132.332 cw(c1.506,131.942) 1.2,132.399 1.327,132.484 cw(c1.633,132.027) 1.422,132.535 1.563,132.593 cw(c1.774,132.085) 1.667,132.625 1.817,132.655 cw(c1.924,132.115) 1.924,132.665 v1(8.76,132.665) v1(18.76,132.665) v1(28.76,132.665) v1(38.76,132.665) v1(47.01,132.665) v1(57.01,132.665) v1(67.01,132.665) 68.076,132.665 cw(c68.076,132.115) 68.184,132.654 68.333,132.625 cw(c68.226,132.085) 68.437,132.593 68.578,132.535 cw(c68.367,132.027) 68.673,132.484 68.8,132.399 cw(c68.494,131.942) 68.883,132.331 68.991,132.223 cw(c68.602,131.834) 69.059,132.14 69.144,132.013 cw(c68.687,131.707) 69.195,131.918 69.253,131.777 cw(c68.745,131.566) 69.285,131.673 69.314,131.524 cw(c68.775,131.416) 69.325,131.416 v1(69.325,131.002) v1(69.325,125.045) v1(69.325,121.924) v1(69.325,117.239) v1(69.325,111.924) v1(69.325,106.52) v1(69.325,101.924) v1(69.325,96.924) v1(69.325,91.924) v1(69.325,86.924) v1(69.325,81.924) v1(69.325,71.924) v1(69.325,61.924) v1(69.325,51.924) v1(69.325,41.924) v1(69.325,37.141) v1(69.325,31.924) v1(69.325,27.682) v1(69.325,21.924) v1(69.325,11.924) v1(69.325,1.924) 69.325,1.869 69.274,1.613 69.174,1.372 69.029,1.155 68.962,1.088 68.924,1.051 68.845,0.971 68.628,0.826 68.386,0.726 68.13,0.675 68,0.675 v1(67.867,0.675) v1(62.8,0.675)
  Bottom Layer w0.25: v1(27.9,40.55) CN19.1@27.9,41.8 ; C107.1@29.1,51.025 C107.1@29.1,51.05 ; v1(29.4,40.55) CN19.7@29.4,41.8 ; CN19.23@33.4,41.8 v1(33.4,43.075) ; CN19.29@34.9,41.8 v1(34.9,43.075) ; CN19.30@35.15,49.35 v1(35.15,50.65) ; CN19.33@35.9,41.86 v1(35.9,43.075) ; v1(36.65,48.1) CN19.36@36.65,49.35 ; CN19.44@38.65,49.35 38.65,50.404 38.796,50.55 39.1,50.55 v1(39.15,50.6) ; CN19.51@40.4,41.8 v1(40.4,43.2) ; CN19.57@41.9,41.8 v1(41.9,43.2) ; CN19.63@43.4,41.8 v1(43.4,43.2) ; CN19.69@44.9,41.8 v1(44.9,43.2) ; CN19.70@45.15,49.35 45.175,49.375 45.175,50.146 45.399,50.37 45.514,50.37 45.719,50.575 v1(45.8,50.575) 45.857,50.632 45.857,50.731 46.106,50.979 46.395,50.979 46.525,51.109 C106.1@46.525,51.125 ; CN19.75@46.4,41.8 v1(46.4,43.2)
  Bottom Layer w0.55: v1(38.05,0.675) v1(34.313,0.675) v1(29.358,0.675) 26.55,0.675 v1(23.05,0.675) v1(14.8,0.675) v1(8.424,0.675) v1(1.924,0.675) cw(c1.924,1.225) 1.817,0.685 1.666,0.715 cw(c1.774,1.255) 1.564,0.746 1.421,0.806 cw(c1.633,1.313) 1.329,0.855 1.199,0.941 cw(c1.506,1.398) 1.118,1.008 1.008,1.118 cw(c1.398,1.506) 0.941,1.199 0.855,1.329 cw(c1.313,1.633) 0.806,1.421 0.746,1.564 cw(c1.255,1.774) 0.715,1.666 0.685,1.817 cw(c1.225,1.924) 0.675,1.924 v1(0.675,2.524) v1(0.675,11.416) v1(0.675,26.707) v1(0.675,36.868) 0.675,41.427 v1(0.675,51.416) v1(0.675,61.416) v1(0.675,66.416) v1(0.675,71.416) v1(0.675,81.416) v1(0.675,91.416) v1(0.675,96.515) v1(0.675,101.416) v1(0.675,106.231) v1(0.675,111.416) v1(0.675,113.899) v1(0.675,121.416) v1(0.675,126.671) v1(0.675,131.416) cw(c1.225,131.416) 0.686,131.524 0.715,131.673 cw(c1.255,131.566) 0.747,131.777 0.806,131.919 cw(c1.313,131.707) 0.855,132.012 0.941,132.14 cw(c1.398,131.834) 1.008,132.222 1.118,132.332 cw(c1.506,131.942) 1.2,132.399 1.327,132.484 cw(c1.633,132.027) 1.422,132.535 1.563,132.593 cw(c1.774,132.085) 1.667,132.625 1.817,132.655 cw(c1.924,132.115) 1.924,132.665 v1(8.76,132.665) v1(18.76,132.665) v1(28.76,132.665) v1(38.76,132.665) v1(47.01,132.665) v1(57.01,132.665) v1(67.01,132.665) 68.076,132.665 cw(c68.076,132.115) 68.184,132.654 68.333,132.625 cw(c68.226,132.085) 68.437,132.593 68.578,132.535 cw(c68.367,132.027) 68.673,132.484 68.8,132.399 cw(c68.494,131.942) 68.883,132.331 68.991,132.223 cw(c68.602,131.834) 69.059,132.14 69.144,132.013 cw(c68.687,131.707) 69.195,131.918 69.253,131.777 cw(c68.745,131.566) 69.285,131.673 69.314,131.524 cw(c68.775,131.416) 69.325,131.416 v1(69.325,131.002) v1(69.325,125.045) v1(69.325,121.924) v1(69.325,117.239) v1(69.325,111.924) v1(69.325,106.52) v1(69.325,101.924) v1(69.325,96.924) v1(69.325,91.924) v1(69.325,86.924) v1(69.325,81.924) v1(69.325,71.924) v1(69.325,61.924) v1(69.325,51.924) v1(69.325,41.924) v1(69.325,37.141) v1(69.325,31.924) v1(69.325,27.682) v1(69.325,21.924) v1(69.325,11.924) v1(69.325,1.924) 69.325,1.869 69.274,1.613 69.174,1.372 69.029,1.155 68.845,0.971 68.758,0.913 68.628,0.826 68.386,0.726 68.13,0.675 68,0.675 v1(67.867,0.675) v1(62.8,0.675) ; v1@69.318,1.879 ccw(c68.775,1.968) 69.318,1.88 v1(69.325,1.924)
  other v1: 29.775,2 35.15,2.025 13.85,2.55 6.25,3.759 11.25,3.759 13.75,3.759 18.75,3.759 21.25,3.759 28.75,3.759 31.25,3.759 33.75,3.759 36.25,3.759 68.75,3.759 23.85,4.225 14.9,4.25 14.175,5.95 64,6.009 7.5,6.259 12.5,6.259 37.5,6.259 23.975,7.775 36,7.925 15,8.05 31.825,8.15 33.375,8.225 20.175,8.675 3.75,8.759 6.25,8.759 13.75,8.759 28.75,8.759 63.75,8.759 66.25,8.759 68.75,8.759 18.575,8.875 20.175,9.375 62.775,9.4 18.4,9.6 66,10.009 20.575,10.1 18.325,10.375 32.65,10.975 30,11 27.5,11.259 65,11.259 67.5,11.259 4.225,11.275 17.125,11.675 18.575,11.975 14.875,12.8 15.725,13.4 17.225,13.4 18.25,13.4 20.55,13.425 8.75,13.759 26.25,13.759 32.7,13.775 68.75,13.759 68,14.009 13.15,14.25 62.775,14.35 28.325,14.475 19.8,14.5 15.725,15.1 17.225,15.1 18.575,15.1 37.725,15.575 7.5,16.259 10,16.259 27.5,16.259 30,16.259 14.775,17.275 22.775,17.95 9.75,18.25 8.75,18.759 28.75,18.759 68.75,18.759 62.75,18.8 55.15,18.9 58.8,18.9 13.05,19.35 32.7,19.35 14.775,20.9 7.5,21.259 10,21.259 57.5,21.259 60,21.259 62.5,21.259 0.675,21.416 37.675,21.8 56,22.009 60,22.009 68,22.009 18.325,22.825 13.15,23.025 32.45,23.3 38.75,23.759 41.25,23.759 56.25,23.759 58.75,23.759 61.25,23.759 68.75,23.759 23.4,24.275 55.075,24.425 14.725,24.675 7.6,25.3 26.85,25.65 13.125,25.95 16.975,25.975 32.025,26.05 25,26.259 57.5,26.259 60,26.259 62.5,26.259 22.15,27.575 27.275,27.65 7.6,27.875 14.725,27.975 13.125,28.25 40.8,28.3 32.65,28.6 56.25,28.759 58.75,28.759 61.25,28.759 14.7,29.625 30.175,29.975 25.3,30.325 7.625,30.525 13.15,30.65 54.875,30.975 27.1,31 52.875,31 14.75,31.25 25,31.259 0.675,31.416 29.725,32.225 61.95,32.7 50.125,32.75 7.675,32.975 13.15,32.975 14.8,33.1 35.825,33.175 36.825,33.175 37.825,33.175 59,33.5 51.575,33.7 53.125,33.7 55.45,33.775 25.575,33.9 35.825,34.175 36.825,34.175 37.825,34.175 50.125,34.325 30.15,34.575 13.1,34.65 27.1,34.65 14.775,34.75 35.825,35.175 36.825,35.175 37.825,35.175 7.5,36.259 10,36.259 53.225,36.3 31.25,36.575 33.875,36.675 56.3,36.675 21.275,36.75 62.1,36.775 13.075,37.65 15.075,37.825 29.325,37.85 25.675,38 27.025,38.025 8.75,38.759 18.75,38.759 32,38.875 62.275,38.9 6.75,39.075 53.15,39.075 50.975,39.2 42.9,39.25 46.425,39.275 51.975,39.45 55.425,39.675 62.275,40.075 21.325,40.5 18.1,41.1 7.175,41.175 15,41.259 53.2,41.375 55.35,41.375 0.675,41.416 20.45,42.3 48.85,42.325 62.725,43.25 7.3,43.325 19.025,43.55 51.125,43.575 56.25,43.759 14.325,44.425 53.2,44.875 62.85,44.9 7.275,45.3 18.975,45.525 61.45,45.9 45.65,46.325 29.05,46.7 49.175,47.075 13.65,47.225 19.1,47.775 7.45,48.025 27.725,48.05 62.675,48.25 47.65,48.3 19.05,49.225 62.85,50.175 8.275,50.5 37.65,50.6 40.15,50.625 19.075,51.075 28.85,51.775 26.9,51.9 30.125,52.375 7.225,52.7 15.35,53.25 55.925,53.25 12.575,53.3 18.95,53.3 53.15,53.6 47.975,53.825 62.275,53.975 8.825,54.05 23.475,54.55 27.125,55 20.575,55.15 15.35,55.175 18.1,55.275 56.125,55.725 48.275,56.3 14.05,56.425 17.95,56.525 61.65,56.55 2.475,57.15 23.225,57.7 13.175,57.725 30.375,57.75 61.675,57.75 18.525,57.775 15.325,57.825 8.425,57.85 17.875,59.025 46.95,59.025 61.7,59.025 15.55,59.075 48.5,60.025 55.6,60.125 61.725,60.275 44.825,60.3 17.8,60.9 30.15,61.5 61.75,61.525 4.425,62.1 12.3,62.175 36.1,62.175 8.55,62.275 19.6,62.85 15.7,63.05 17.8,63.075 41.525,63.225 39.55,63.425 34.15,63.475 37.025,63.5 8.475,64.625 12.35,64.625 61.775,64.775 15.65,64.8 25.725,65.225 43.675,65.225 54.75,65.75 56.2,65.75 50.975,65.775 22.175,65.9 42.3,66.25 19.55,66.425 32.1,66.525 61.75,66.625 47.3,66.75 36.275,67.05 12.325,67.075 39.45,67.075 8.225,67.175 15.6,67.275 2.325,67.35 16.925,67.45 25.65,67.75 30.375,67.875 61.75,67.9 56.1,68.025 61.725,69.075 15.725,69.425 21.225,69.45 18.35,69.475 28.975,69.525 7.925,69.95 41.275,70.025 12.375,70.05 61.775,70.35 57.375,70.525 29.1,70.85 47.4,71.7 36.75,71.725 61.725,71.725 39.975,71.975 18.175,72.025 20.05,72.025 21.15,72.025 22.25,72.025 13.25,72.175 15.775,72.25 3.825,72.375 44.65,72.75 61.75,72.925 53.45,73 8,73.1 55.875,73.1 27.05,73.4 39.55,73.9 29.05,74 51.7,74.175 61.75,74.275 8.775,74.425 36.225,74.75 41.925,74.875 3.725,74.95 61.975,75.925 31.1,76.325 42.025,76.475 26.3,76.625 55.625,76.8 57.4,76.8 51.725,76.825 53.4,76.925 44.4,77.4 13.35,77.85 25.875,78.075 17.25,78.1 61.575,78.5 53.475,78.55 55.625,78.6 57.4,78.675 43.275,79 17.85,80.325 39.3,80.325 19.075,80.4 32.15,80.5 36.4,80.525 55.125,80.6 15.925,80.675 53.475,80.7 45.75,80.725 24.575,80.775 61.725,80.775 57.325,81.625 17.025,81.7 35.925,83.05 37.575,83.075 13.275,83.125 30.2,83.15 12.275,83.3 48.975,83.425 56.425,83.6 22.55,83.725 19.2,84 29.025,84.25 30.4,84.525 54.7,84.725 20.55,85.125 24.4,85.275 40.425,85.425 38.375,85.45 36.35,85.475 43.75,85.55 51.7,85.775 45.925,85.95 49.05,85.95 61.55,86.025 57.25,86.45 1.475,86.6 42.2,86.725 37.725,86.825 39.125,86.825 40.575,86.825 15.55,87.15 29.575,87.425 31.175,87.425 20.9,87.5 19.175,87.55 24.125,88.025 16.8,88.275 57.425,88.4 40.35,88.475 41.575,88.475 50.9,88.55 47.15,88.575 15.55,88.675 61.425,88.725 29.6,89.2 57.05,89.775 21.35,89.85 19.05,89.875 40.45,90.125 29.6,90.175 51.225,90.825 56.35,91.075 31.15,91.25 19.425,91.675 40.975,92.05 21.5,92.275 15.05,92.35 4.45,92.725 11.825,92.85 24.625,93.125 51.925,93.2 15.9,93.3 45.5,93.75 46.5,93.75 53.75,93.759 56.25,93.759 8.55,93.825 61.55,93.9 28.55,94.15 15.025,94.35 34.05,94.425 45.5,94.75 46.5,94.75 47.5,94.75 30.525,95.225 15.9,95.25 20,95.25 24,95.25 52.35,95.725 43.5,95.75 44.5,95.75 45.5,95.75 46.5,95.75 57.3,96.175 32.625,96.2 19,96.25 20,96.25 21,96.25 24,96.25 15,96.259 30.5,96.325 37.85,96.675 43.5,97 44.5,97 50.25,97.025 53.875,97.1 62.65,97.175 19,97.25 20,97.25 22,97.25 23,97.25 24,97.25 25,97.25 44,97.75 15.025,97.9 40.75,97.9 18.25,98.25 19,98.25 20,98.25 24,98.25 25,98.25 8.7,98.375 10.8,98.375 52.05,98.45 43.5,98.5 44.5,98.5 57.025,98.575 35.65,98.625 15.95,98.7 18.25,99.25 27.2,99.425 43.5,99.5 44.5,99.5 45.5,99.5 52.575,99.975 62.15,100.075 30.375,101.075 15.05,102.05 18.975,102.25 8.275,102.5 34.225,102.825 51.8,102.875 45.275,103.25 32.05,103.275 42.85,103.275 4.575,103.65 23.75,103.759 48.75,103.759 62.425,103.775 67.95,103.975 6.4,105.5 43.35,106.225 57.5,106.259 64.625,107.625 14.675,108.05 20.15,108.05 1.7,108.3 31.87,108.4 21.875,108.575 17.125,108.6 8.75,108.759 57.925,108.875 31.87,109.15 36.2,109.145 36.95,109.145 46.2,109.15 25.95,109.375 62.475,109.925 22.155,110.1 2.675,110.125 5.15,110.15 8.575,110.225 12.575,110.25 14.575,110.9 47.225,111 35.3,111.125 30.75,111.35 67.075,111.575 19.65,111.8 53.8,111.975 61.475,112.475 35.25,113.175 33.775,113.95 14.1,113.975 50.65,114.3 54.65,114.9 4.775,116.825 44.36,117.175 47.5,117.65 48.25,117.65 37.625,117.675 38.375,117.675 12.7,118.075 37.275,118.25 44.4,118.375 35.8,118.5 49.6,118.5 33,118.575 37.275,119 15.528,119.072 60.35,119.075 44.4,119.125 14,119.2 44.925,119.9 12.225,120.625 45.675,120.675 53.175,120.9 33.3,121.075 4.725,121.925 55.6,122.1 48.825,122.15 60.25,122.25 43.3,122.625 36.85,123.525 33.75,123.6 30,123.725 8.75,123.759 11.65,124.125 41.1,124.15 4.775,124.325 64.275,124.475 30.9,125.3 28.625,125.375 16.75,125.475 9.5,125.625 47.55,125.85 59.375,125.85 54.175,125.875 56.225,125.9 50,126.259 15.275,126.375 63.75,127.4 16.65,127.725 6.25,128.759 63.75,128.759 68.75,128.759 18.925,128.8 23.3,129 27.625,129.1 31.35,129.375 49.65,130.025 17.4,130.5 35.525,131.175 5,131.259 12.5,131.259 15,131.259 65,131.259
LED1: SB8.1 U1.37 | length 36
  Top Layer w0.12: U1.37@45.975,62.15 47.05,62.15 47.55,61.65 49.775,61.65 v1(50.25,62.125) ; 54.225,89.7 54.85,89.7 v1(54.875,89.725)
  Bottom Layer w0.12: v1(50.25,62.125) 50.25,80.625 50.475,80.85 50.475,87.325 52.875,89.725 v1(54.875,89.725)
LED2: LD2.2 U1.10 | length 81.4
  Top Layer w0.12: U1.10@30.9,60.175 v1(30.9,62) ; v1(54.3,116.3) LD2.2@54.3,117.35
  Signal Layer 2 w0.12: v1(34.525,115.45) 35.85,116.775 37.725,116.775 39.5,115 53,115 v1(54.3,116.3)
  Bottom Layer w0.12: v1(30.9,62) 30.9,64.161 32.95,66.211 32.95,83.725 30.55,86.125 30.55,92.875 33.325,95.65 33.325,108.05 34.525,109.25 v1(34.525,115.45)
LED3: LD3.2 U1.4 | length 85.5
  Top Layer w0.12: U1.4@27.9,60.175 v1(27.9,61.5) ; v1(56.85,116.3) LD3.2@56.85,117.35
  Signal Layer 2 w0.12: v1(33.075,116.475) 33.725,117.125 38.025,117.125 38.678,116.472 47.747,116.472 48.525,117.25 55.9,117.25 v1(56.85,116.3)
  Bottom Layer w0.12: v1(27.9,61.5) 27.9,69.675 28.475,70.25 28.475,79 27.295,80.18 27.295,85.752 29.125,87.582 29.125,110.431 32.15,113.456 32.15,115.55 v1(33.075,116.475)
MEM_GPIO: CN12.15 CN19.40 | length 39.1
  Top Layer w0.12: v1(49.925,35.57) 54.13,35.57 54.35,35.35 55.2,35.35 55.42,35.57 CN12.15@64.206,35.57
  Bottom Layer w0.12: CN19.40@37.65,49.35 37.65,48.118 38.25,47.518 38.25,45.892 38.822,45.32 48.594,45.32 49.925,43.989 v1(49.925,35.57)
MEM_LED1: CN12.11 CN19.42 | length 33.2
  Top Layer w0.12: v1(50.558,40.638) CN12.11@64.194,40.638
  Signal Layer 2 w0.12: CN12.11@64.194,40.638 CN12.11@64.206,40.65
  Bottom Layer w0.12: CN19.42@38.15,49.35 38.15,47.958 38.49,47.618 38.49,45.991 38.921,45.56 48.694,45.56 50.558,43.695 v1(50.558,40.638)
MEM_LED2: CN12.13 CN19.38 | length 36.8
  Top Layer w0.12: v1(49.45,38.11) CN12.13@64.206,38.11
  Bottom Layer w0.12: CN19.38@37.15,49.35 37.15,46.652 38.722,45.08 48.495,45.08 49.45,44.125 v1(49.45,38.11)
NetC4_2: C4.2 TP9.1 U2.F13 | length 6
  Top Layer w0.12: TP9.1@18.15,125.6 C4.2@19.25,125.6 19.395,125.455 19.395,123.199 19.594,123 21.325,123 U2.F13@21.65,122.675
NetC7_2: C7.2 TP4.1 U2.J14 | length 5.5
  Top Layer w0.12: U2.J14@23.6,123.325 23.925,123.65 23.925,124.235 24.7,125.01 C7.2@24.7,125.6 24.725,125.6 25.14,126.015 25.14,127.615 TP4.1@25.525,128
NetC12_2: C12.2 TP13.1 U2.M10 | length 6.9
  Top Layer w0.12: C12.2@29.1,122.75 TP13.1@29.1,123.775
  Top Layer w0.2: v1(24.825,121.145) 25.245,120.725 U2.M10@25.55,120.725 ; v1(28.35,122.75) C12.2@29.1,122.75
  Bottom Layer w0.2: v1(24.825,121.145) 26.43,122.75 v1(28.35,122.75)
NetC19_2: C19.2 TP23.1 U8.1 | length 2.5
  Top Layer w0.12: U8.1@40.75,117.275 40.75,117.375 41.405,118.03 41.405,118.155 41.6,118.35 C19.2@41.625,118.35 TP23.1@42.65,118.35
NetC34_2: C34.2 D1.2 D2.2 TP36.1 U11.3 U11.5 | length 2.3
  Top Layer w0.12: TP36.1@38,107.075 38.38,107.455 D2.2@38.38,109.25
NetC43_2: C43.2 C45.2 R60.2 U15.5 U15.6
NetC44_2: C44.2 C46.2 R61.2 U16.1 U16.2 U16.6 | length 12.7
  Top Layer w0.3: U16.2@22.4,98.65 22.4,99.199 22.576,99.375 23.2,99.375 ; U16.1@23.2,98.625 U16.1@23.2,98.65 23.2,99.375 ; v1(24,99.075) 23.699,99.375 23.2,99.375
  Signal Layer 2 w0.3: v1(21.475,93.9) 22.075,94.5 24.225,94.5 25.65,95.925 25.65,98.675 25.25,99.075 v1(24,99.075)
NetC47_1: C47.1 CN5.8 CN10.7 SB10.2 | length 20
  Top Layer w0.25: SB10.2@53.725,86.825 54.125,86.825 54.275,86.975 54.275,87.975 v1(56.125,87.975)
  Bottom Layer w0.25: v1(56.125,87.975) 57.325,89.175 59.9,89.175 62,91.275 62,91.784 CN10.7@64.206,93.99 62.682,95.514 CN5.8@59.126,95.514
NetC79_2: C79.2 R1.1 X2.2 | length 3.2
  Top Layer w0.12: C79.2@28.825,53.18 28.975,53.33 28.975,53.675 29.375,54.075 29.375,54.505 29.425,54.555 R1.1@29.425,56.13
NetC81_2: C81.2 R2.1 X2.1 | length 3.2
  Top Layer w0.12: R2.1@30.85,56.13 30.85,54.53 30.865,54.515 30.865,54.035 31.275,53.625 31.275,53.33 C81.2@31.425,53.18
NetC82_1: C82.1 R4.2 X3.3 | length 2.4
  Top Layer w0.12: R4.2@37.906,54.389 X3.3@37.906,53.014 C82.1@38.956,53.014
NetC83_1: C83.1 R3.2 X3.1 | length 5.1
  Top Layer w0.12: 35.925,52.264 X3.1@36.856,52.264 36.931,52.189 C83.1@36.931,51.339 ; 35.925,52.275 35.55,52.65 35.55,53.25 35.829,53.529 36.554,53.529 36.906,53.881 R3.2@36.906,54.389
NetC85_2: C85.2 C86.2 TP55.1 U17.6 | length 4.2
  Top Layer w0.12: U17.6@38.775,35.425 39.084,35.425 39.609,35.95 C86.2@40.725,35.95 C85.2@40.725,36.825 40.1,36.825 TP55.1@39.75,37.175
NetC87_2: C87.2 SB14.2 U17.5 X4.3 | length 68
  Top Layer w0.12: v1(20,76.125) 20.838,76.125 20.963,76 SB14.2@20.975,76 ; U17.5@38.775,34.925 39.9,34.925 40.1,34.725 X4.3@42.7,34.725 42.7,35.525 42.83,35.655 42.855,35.655 43.05,35.85 C87.2@43.05,35.875 v1(42.375,35.875)
  Signal Layer 2 w0.12: v1(23.825,35.875) 23.885,35.875 24.11,36.1 42.09,36.1 42.315,35.875 v1(42.375,35.875)
  Bottom Layer w0.12: v1(20,76.125) 19.455,75.58 19.455,68.109 20.43,67.135 20.43,60.899 22.695,58.634 22.695,46.434 23.61,45.519 23.61,36.16 23.825,35.945 v1(23.825,35.875)
NetC88_2: C88.2 C90.2 C91.2 C92.2 C94.2 C95.2 L4.2 R84.2 R85.2 R86.2 R87.2 TP57.1 U17.1 U17.19 U18.5 U19.2 U19.7 | length 27.7
  Top Layer w0.2: TP57.1@33.925,28.9 33.925,30.275 v1(34.425,30.775)
  Top Layer w0.25: v1(34.425,30.775) C92.2@35.125,30.775
  Top Layer w0.3: C92.2@35.125,30.775 35.125,31.437 35.575,31.887 U17.19@35.575,32.225 ; U17.1@38.775,32.925 39.054,32.925 39.729,32.25 C88.2@40.725,32.25 40.8,32.175 C91.2@40.8,31.125 ; v1(40.075,31.125) C91.2@40.8,31.125 ; L4.2@40.975,29.675 40.8,29.85 C91.2@40.8,31.125 ; C90.2@50.35,31.425 v1(51,31.425)
  Top Layer w0.5: R84.2@35.1,26.825 v1(39.125,26.825) ; C94.2@40.125,26.4 v1(40.825,26.4) ; U19.7@44.15,27.2 v1(44.15,28.4) ; v1(47.25,31.2) U18.5@47.25,32.2 ; U19.2@50.5,27.2 v1(50.5,28.4) ; v1(53.675,26.4) C95.2@54.375,26.4
  Signal Layer 2 w0.5: v1(50.5,28.4) 52.5,26.4 v1(53.675,26.4)
  Bottom Layer w0.5: v1(40.825,26.4) 42.15,26.4 v1(44.15,28.4)
NetC89_2: C89.2 R79.1 X4.1 | length 3.7
  Top Layer w0.12: R79.1@41.625,33.85 41.825,34.05 43.15,34.05 43.75,33.45 X4.1@43.75,33.375 43.675,33.3 C89.2@43.675,32.25
NetC96_1: C96.1 Q1.4 R115.2 U21.5 | length 9
  Top Layer w0.12: v1(20.3,20.75) 20.525,20.525 U21.5@21.325,20.525 ; Q1.4@20.975,23.375 C96.1@22.5,23.375 v1(23.325,23.375)
  Top Layer w0.3: v1(23.325,23.375) R115.2@24.3,23.375
  Signal Layer 2 w0.12: v1(20.3,20.75) 21.425,20.75 23.325,22.65 v1(23.325,23.375)
NetC97_1: C97.1 CN13.A5 U21.7 | length 16.8
  Top Layer w0.12: v1(16.25,9.4) 17.4,9.4 18.53,8.27 18.53,7.985 CN13.A5@18.62,7.895 ; v1(20.1,17.5) C97.1@20.775,17.5 20.775,18.377 20.973,18.575 21.95,18.575 22.25,18.875 U21.7@22.25,19.1
  Signal Layer 2 w0.12: v1(16.25,9.4) 15.65,10 15.65,11.15 17.75,13.25 17.75,15.15 v1(20.1,17.5)
NetC98_1: C98.1 CN13.B5 U21.9 | length 17.5
  Top Layer w0.12: CN13.B5@19.87,6.195 19.945,6.27 19.945,6.635 20.005,6.695 20.005,7.07 v1(20.02,7.085) ; U21.9@23.25,19.1 23.25,18.875 23.55,18.575 23.95,18.575 24.45,18.075 C98.1@24.45,17.5 v1(25.4,17.5)
  Bottom Layer w0.12: v1(20.02,7.085) 20.102,7.167 20.102,7.352 22.4,9.65 22.4,15.504 24.396,17.5 v1(25.4,17.5)
NetC99_1: C99.1 D3.2 U21.8 | length 3.6
  Top Layer w0.12: C99.1@21.9,17.425 21.915,17.425 C99.1@22.025,17.425 ; U21.8@22.75,19.1 22.75,18.575 22.03,17.855 22.03,17.43 C99.1@22.025,17.425 ; D3.2@23.3,17.2 D3.2@23.3,17.375 23.25,17.425 C99.1@22.025,17.425
NetC100_2: C100.2 R89.1 R92.1 R93.1 R94.1 | length 25.4
  Top Layer w0.5: R92.1@38,18.95 R93.1@39.05,18.95 R94.1@40.125,18.95 v1(40.125,19.713) R89.1@40.125,20.475 ; v1(58.3,15.75) C100.2@60.275,15.75
  Signal Layer 2 w0.5: v1(40.125,19.713) 40.139,19.713 40.751,19.1 52.9,19.1 56.25,15.75 v1(58.3,15.75)
NetCN1_A5: CN1.A5 R13.2 R14.1 | length 11.5
  Top Layer w0.12: R13.2@35.4,125.775 35.525,125.9 R14.1@36.35,125.9 v1(37.2,125.9) ; CN1.A5@43.635,125.44 43.635,123.89 v1(43.925,123.6)
  Signal Layer 2 w0.12: v1(37.2,125.9) 37.65,125.45 42.075,125.45 v1(43.925,123.6)
NetCN1_B5: CN1.B5 R5.1 R6.2 | length 10.2
  Top Layer w0.12: R6.2@35.4,126.85 36.225,126.85 R5.1@36.35,126.725 v1(37.2,126.725) ; v1(42.235,126.25) 42.25,126.265 42.25,126.64 42.31,126.7 42.31,127.065 CN1.B5@42.385,127.14
  Signal Layer 2 w0.12: v1(37.2,126.725) 37.2,127.875 37.825,128.5 39.985,128.5 v1(42.235,126.25)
